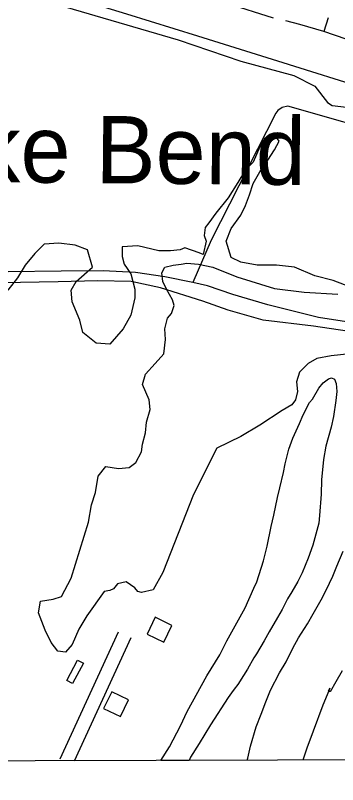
# Model space of a CAD drawing. Extents: x 3361039 to 3398939, y 576572 to 602007.
# Drawn here: x 3383670 to 3384364, y 581957 to 583615 of the extents above; entities that cross this region are included whole.
import ezdxf

# ---------------------------------------------------------------- set-up
doc = ezdxf.new("R2010")
doc.units = 0
for name, color, linetype in [('V-BLDG-OTLN', 7, 'Continuous'), ('V-GRID-FRAM', 7, 'Continuous'), ('V-RAIL-TRAK', 7, 'Continuous'), ('V-ROAD-CNTR', 7, 'Continuous'), ('V-SITE-VEGE', 7, 'Continuous'), ('V-TOPO-GNAM-IDEN', 7, 'Continuous'), ('V-TOPO-SHOR', 7, 'Continuous')]:
    doc.layers.add(name, color=color, linetype=linetype)

msp = doc.modelspace()

# ---------------------------------------------------------------- linework, layer by layer
at = {"layer": 'V-BLDG-OTLN'}
for points in [[(3383970.6, 582317.6), (3383953.3, 582281.6), (3383989.4, 582264.3), (3384006.7, 582300.3)], [(3383816.1, 582219), (3383792.9, 582174.7), (3383780.5, 582181.2), (3383803.7, 582225.5)], [(3383877.1, 582156.9), (3383859.8, 582120.8), (3383895.9, 582103.5), (3383913.2, 582139.6)]]:
    msp.add_lwpolyline(points, close=True, dxfattribs=at)
at = {"layer": 'V-GRID-FRAM'}
msp.add_lwpolyline([(3365114.8, 600140.3), (3396720.3, 600227.7), (3396778.5, 582044.3), (3365157.1, 581956.9), (3365114.8, 600140.3)], dxfattribs=at)
at = {"layer": 'V-RAIL-TRAK'}
msp.add_lwpolyline([(3384441, 583451.9), (3384235.3, 583516.2), (3384062.5, 583570.7), (3383909.9, 583618), (3383730.2, 583673.2), (3383554.2, 583728.4), (3383358, 583790.6), (3383176.4, 583848.4), (3383057.3, 583883.9), (3382930.2, 583923.7), (3382756.7, 583978.2), (3382567.5, 584036.6), (3382374.4, 584096.3), (3382221.9, 584143.7), (3382018.7, 584207.2), (3381857.3, 584257.2), (3381679.5, 584313), (3381485.2, 584372.7), (3381264.3, 584442.2), (3381071.9, 584501.2)], dxfattribs=at)
at = {"layer": 'V-ROAD-CNTR'}
for points in [[(3383891.4, 582285.8), (3383765.6, 582011.5)], [(3383918.7, 582273.3), (3383796.6, 582007.2)]]:
    msp.add_lwpolyline(points, dxfattribs=at)
at = {"layer": 'V-SITE-VEGE'}
for p, q in [((3384323.2, 582811.3), (3384332.9, 582822.8)), ((3384332.9, 582822.8), (3384343.9, 582831.7)), ((3384343.9, 582831.7), (3384350.4, 582833.6)), ((3384350.4, 582833.6), (3384356.8, 582831)), ((3384356.8, 582831), (3384360.6, 582821.9)), ((3384309.5, 582788.2), (3384323.2, 582811.3)), ((3384360.6, 582821.9), (3384362.4, 582804.5)), ((3384362.4, 582804.5), (3384360.3, 582785.2)), ((3384289.9, 582754.2), (3384303.6, 582780.5)), ((3384303.6, 582780.5), (3384309.5, 582788.2)), ((3384360.3, 582785.2), (3384354.9, 582750.5)), ((3384281.4, 582735.6), (3384289.9, 582754.2)), ((3384354.9, 582750.5), (3384349.6, 582727.3)), ((3384267.7, 582704.1), (3384281.4, 582735.6)), ((3384349.6, 582727.3), (3384338.4, 582686.9)), ((3384259.1, 582680.3), (3384267.7, 582704.1)), ((3384250.5, 582648.8), (3384259.1, 582680.3)), ((3384338.4, 582686.9), (3384333.7, 582657.9)), ((3384333.7, 582657.9), (3384328.9, 582614.1)), ((3384247.2, 582629.5), (3384250.5, 582648.8)), ((3384239.2, 582596.7), (3384247.2, 582629.5)), ((3384328.9, 582614.1), (3384328.6, 582583.2)), ((3384234.6, 582576.2), (3384239.2, 582596.7)), ((3384226.6, 582537.6), (3384234.6, 582576.2)), ((3384328.6, 582583.2), (3384325.1, 582536.9)), ((3384220.6, 582513.1), (3384226.6, 582537.6)), ((3384325.1, 582536.9), (3384323.1, 582520.8)), ((3384211.9, 582470.7), (3384220.6, 582513.1)), ((3384323.1, 582520.8), (3384310.5, 582473.2)), ((3384204, 582439.2), (3384211.9, 582470.7)), ((3384310.5, 582473.2), (3384300.6, 582445)), ((3384300.6, 582445), (3384287.5, 582413.5)), ((3384190.1, 582394.2), (3384204, 582439.2)), ((3384287.5, 582413.5), (3384278.4, 582394.9)), ((3384183.6, 582380.7), (3384190.1, 582394.2)), ((3384278.4, 582394.9), (3384265.3, 582372.4)), ((3384164.6, 582337.7), (3384183.6, 582380.7)), ((3384265.3, 582372.4), (3384256.2, 582357.7)), ((3384256.2, 582357.7), (3384244.5, 582334.6)), ((3384125.5, 582267.1), (3384164.6, 582337.7)), ((3384244.5, 582334.6), (3384234, 582317.3)), ((3384234, 582317.3), (3384216.4, 582286.5)), ((3384216.4, 582286.5), (3384205.3, 582266.6)), ((3384109.8, 582237), (3384125.5, 582267.1)), ((3384205.3, 582266.6), (3384189, 582239)), ((3384082.4, 582191.4), (3384109.8, 582237)), ((3384183.2, 582230), (3384169.5, 582205.6)), ((3384189, 582239), (3384183.2, 582230)), ((3384161, 582192.2), (3384148.6, 582172.9)), ((3384169.5, 582205.6), (3384161, 582192.2)), ((3384040, 582114.4), (3384082.4, 582191.4)), ((3384140.8, 582162.7), (3384135.6, 582155)), ((3384148.6, 582172.9), (3384140.8, 582162.7)), ((3384127.8, 582144.7), (3384090.1, 582085.8)), ((3384135.6, 582155), (3384127.8, 582144.7)), ((3384025.7, 582083.6), (3384040, 582114.4)), ((3384001.5, 582038.1), (3384025.7, 582083.6)), ((3384090.1, 582085.8), (3384065.3, 582045.4)), ((3384065.3, 582045.4), (3384047.1, 582015.9)), ((3383983, 582009), (3384001.5, 582038.1)), ((3384047.1, 582015.9), (3384043.7, 582009.1)), ((3384043.7, 582009.1), (3383983, 582009))]:
    msp.add_line(p, q, dxfattribs=at)
for points in [[(3383729.9, 583647.5), (3384020.3, 583562.3), (3384155.1, 583516.7), (3384269.2, 583485.6), (3384314.8, 583462.7), (3384341.8, 583427.4), (3384352.2, 583421.2), (3384383.3, 583417.1)], [(3384227.7, 583325.7), (3384238.1, 583344.4), (3384229.8, 583354.8), (3384207, 583350.6), (3384196.6, 583332), (3384182.1, 583298.7), (3384165.5, 583282.1), (3384148.9, 583255.2), (3384128.2, 583221.9), (3384101.2, 583188.7), (3384086.7, 583168), (3384078.4, 583157.6), (3384076.3, 583141), (3384080.5, 583128.5), (3384074.2, 583099.5), (3384065.9, 583103.6), (3384034.8, 583114), (3384024.5, 583109.9), (3384003.7, 583107.8), (3383978.8, 583107.8), (3383933.2, 583118.2), (3383900, 583116.1), (3383900, 583095.3), (3383904.2, 583078.7), (3383918.7, 583058), (3383927, 583024.8), (3383927, 583006.1), (3383918.7, 582968.7), (3383902.1, 582939.7), (3383873, 582906.4), (3383844, 582908.5), (3383815, 582931.4), (3383808.7, 582958.3), (3383792.2, 582997.8), (3383790.1, 583022.7), (3383800.5, 583041.4), (3383835.7, 583072.5), (3383825.3, 583109.9), (3383798.4, 583120.2), (3383763.1, 583124.4), (3383732, 583122.3), (3383711.3, 583101.6), (3383690.5, 583076.7), (3383673.9, 583049.7), (3383653.2, 583022.7)], [(3384393.6, 583028.9), (3384354.2, 583043.4), (3384314.8, 583053.8), (3384271.3, 583072.5), (3384231.9, 583076.7), (3384190.4, 583076.7), (3384155.1, 583082.9), (3384134.4, 583093.3), (3384124, 583128.5), (3384134.4, 583155.5), (3384155.1, 583184.6), (3384165.5, 583205.3), (3384173.8, 583228.2), (3384182.1, 583253.1), (3384196.6, 583278), (3384213.2, 583302.9), (3384227.7, 583325.7)], [(3384410.2, 582887.8), (3384350.1, 582881.5), (3384319, 582875.3), (3384300.3, 582864.9), (3384281.6, 582846.3), (3384275.4, 582825.5), (3384277.5, 582804.7), (3384273.3, 582786.1), (3384265, 582775.7), (3384244.3, 582763.2), (3384196.6, 582732.1), (3384155.1, 582707.2), (3384103.3, 582682.3), (3384053.5, 582582.6), (3383987.1, 582414.5), (3383966.4, 582377.2), (3383941.5, 582370.9), (3383933.2, 582373), (3383927, 582381.3), (3383908.3, 582393.8), (3383889.6, 582389.6), (3383881.3, 582379.2), (3383873, 582375.1), (3383860.6, 582373), (3383823.3, 582321.1), (3383806.7, 582292.1), (3383792.2, 582258.8), (3383777.6, 582242.2), (3383761, 582244.3), (3383746.5, 582263), (3383734.1, 582290), (3383719.6, 582327.3), (3383723.7, 582352.2), (3383750.7, 582356.4), (3383769.3, 582362.6), (3383790.1, 582402.1), (3383827.4, 582522.5), (3383833.6, 582559.8), (3383841.9, 582586.8), (3383848.2, 582622.1), (3383864.7, 582642.8), (3383891.7, 582638.7), (3383914.5, 582640.8), (3383929, 582651.1), (3383941.5, 582674), (3383943.6, 582690.6), (3383949.8, 582715.5), (3383951.9, 582738.3), (3383960.2, 582765.3), (3383958.1, 582786.1), (3383943.6, 582819.3), (3383949.8, 582842.1), (3383970.5, 582864.9), (3383989.2, 582885.7), (3383993.3, 582916.8), (3383991.3, 582939.7), (3383997.5, 582962.5), (3384005.8, 582972.9), (3384012, 582989.5), (3384007.9, 583001.9), (3383995.4, 583024.8), (3383987.1, 583041.4), (3383985, 583060), (3383991.3, 583072.5), (3384009.9, 583076.7), (3384026.5, 583078.7), (3384039, 583080.8), (3384063.9, 583078.7), (3384095, 583072.5), (3384146.8, 583051.7), (3384227.7, 583026.8), (3384292, 583018.5), (3384364.6, 583014.4)], [(3384169.2, 582009.5), (3384170.1, 582013.7), (3384176.1, 582040.1), (3384188.6, 582081.8), (3384199.1, 582108.8), (3384208.9, 582135.2), (3384219.4, 582160.8), (3384239, 582198.1), (3384252.7, 582221.8), (3384267.7, 582251.3), (3384279.5, 582273.1), (3384299, 582303.9), (3384311.4, 582325.1), (3384328.3, 582355.2), (3384339.4, 582375.8), (3384353.2, 582406.6), (3384362.3, 582427.8), (3384376.1, 582460.5)], [(3384373.6, 582202.3), (3384359.9, 582178.5), (3384347.6, 582156.7), (3384344.6, 582159.2), (3384347, 582165.1), (3384344.3, 582159.3), (3384344.6, 582159.2), (3384331.9, 582127.9), (3384311.5, 582072), (3384297.8, 582035.4), (3384288.9, 582009.8)]]:
    msp.add_lwpolyline(points, dxfattribs=at)
msp.add_lwpolyline([(3384344.6, 582159.2), (3384344.3, 582159.3), (3384347, 582165.1)], close=True, dxfattribs=at)
at = {"layer": 'V-TOPO-SHOR'}
msp.add_line((3384343.8, 583609.9), (3384333.9, 583580.3), dxfattribs=at)
for points in [[(3384225.8, 583609.3), (3384126.2, 583640.7), (3384010.6, 583676.4), (3383876.2, 583719.3), (3383734.8, 583766.3), (3383576, 583814.9), (3383386.5, 583874.9), (3383310.7, 583908.9), (3383305.8, 583905.4), (3383287.4, 583872.8), (3383278.8, 583847)], [(3384579, 583497.9), (3384457.8, 583537.9), (3384333.9, 583580.3), (3384282.3, 583595.6), (3384252.3, 583603.5)], [(3384498.5, 583350.2), (3384256.9, 583419.7), (3384244.4, 583417), (3384234.7, 583410.2), (3384230.5, 583404.6), (3384091.6, 583130.3), (3384051.7, 583039.1)], [(3384462, 582942.4), (3384322.4, 582963.6), (3384213.5, 582991.1), (3384137.9, 583013.2), (3384083.2, 583032.5), (3384051.7, 583039.1), (3383991.9, 583051.5), (3383928.7, 583061), (3383858.8, 583064.8), (3383768.1, 583064.1), (3383653.8, 583062.3)], [(3384457.3, 582923.5), (3384311.8, 582945.4), (3384203.5, 582957.9), (3384127.9, 582980), (3384073.2, 582999.3), (3383982.6, 583028), (3383919.4, 583041.5), (3383846.9, 583042.7), (3383762, 583040.7), (3383639.9, 583038.9)]]:
    msp.add_lwpolyline(points, dxfattribs=at)

# ---------------------------------------------------------------- texts
at = {"layer": 'V-TOPO-GNAM-IDEN'}
msp.add_text('Smoke Bend', height=145, rotation=359.4818, dxfattribs=at).set_placement((3383184.6, 583259.6))

doc.saveas('drawing.dxf')
